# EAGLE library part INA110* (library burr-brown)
Instrumentation Amplifier Fast-Settling FET-Input
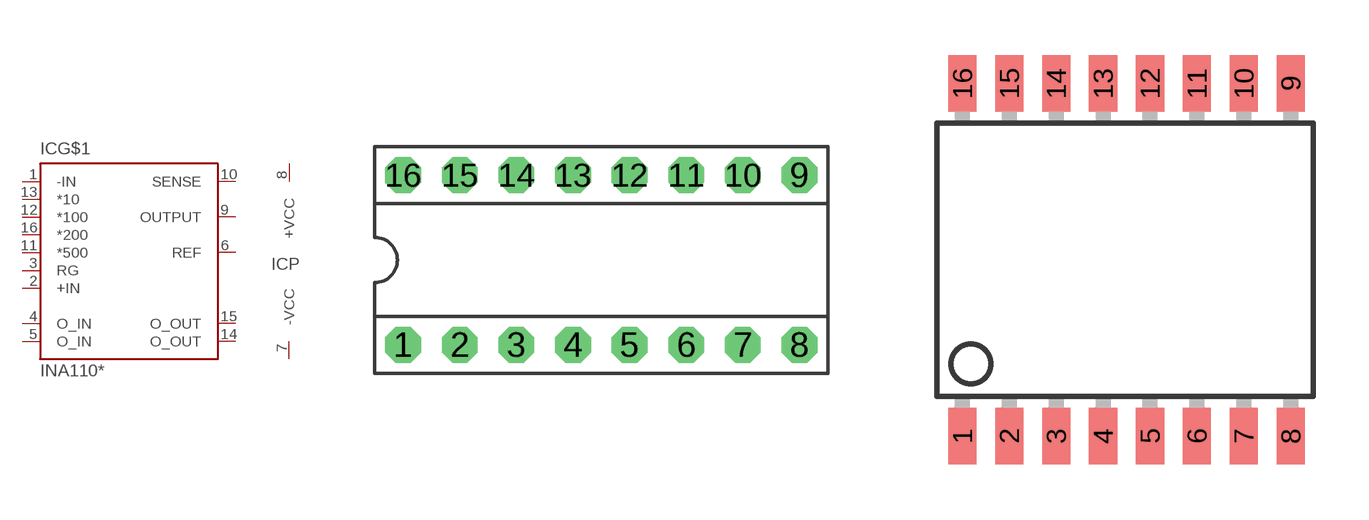
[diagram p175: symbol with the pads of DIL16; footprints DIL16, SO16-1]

Designator prefix IC; gates G$1=INA110 P=+-VCC

## INA110KP (MF: TEXAS INSTRUMENTS; MPN: INA110KP; OC_FARNELL: 1097535; OC_NEWARK: 74K3807)  [DIL16]
1  G$1:-IN  in
2  G$1:+IN  in
3  G$1:RG  pas
4  G$1:O_IN  pas
5  G$1:O_IN  pas
6  G$1:REF  in
7  P:-VCC  pwr
8  P:+VCC  pwr
9  G$1:OUTPUT  out
10  G$1:SENSE  in
11  G$1:*500  pas
12  G$1:*100  pas
13  G$1:*10  pas
14  G$1:O_OUT  pas
15  G$1:O_OUT  pas
16  G$1:*200  pas

## INA110KU (MF: TEXAS INSTRUMENTS; MPN: INA110KU; OC_FARNELL: 1212396; OC_NEWARK: 04M4539)  [SO16-1]
Pads as for DIL16

## Footprint DIL16 (pad centres in mm)
Dual In Line
drill 0.813 pad 1.6 octagon: 1 -8.89,-3.81; 2 -6.35,-3.81; 3 -3.81,-3.81; 4 -1.27,-3.81; 5 1.27,-3.81; 6 3.81,-3.81; 7 6.35,-3.81; 8 8.89,-3.81; 9 8.89,3.81; 10 6.35,3.81; 11 3.81,3.81; 12 1.27,3.81; 13 -1.27,3.81; 14 -3.81,3.81; 15 -6.35,3.81; 16 -8.89,3.81

## Footprint SO16-1 (pad centres in mm)
Small Outline Package
smd 0.762 x 1.524: 1 -4.445,-4.775; 2 -3.175,-4.775; 3 -1.905,-4.775; 4 -0.635,-4.775; 5 0.635,-4.775; 6 1.905,-4.775; 7 3.175,-4.775; 8 4.445,-4.775; 9 4.445,4.775; 10 3.175,4.775; 11 1.905,4.775; 12 0.635,4.775; 13 -0.635,4.775; 14 -1.905,4.775; 15 -3.175,4.775; 16 -4.445,4.775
